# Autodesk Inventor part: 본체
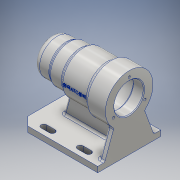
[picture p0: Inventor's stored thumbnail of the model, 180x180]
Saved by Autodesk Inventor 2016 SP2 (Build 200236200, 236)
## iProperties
Created: 2017-09
Part Number: 본체
Material: 알루미늄 6061
Document SubType Name: 모델링
Designer: Administrator
Density: 2.7 g/cm^3
Appearance: 알루미늄 - 평지
Sheet Metal Rule: 기본값_mm
Mass: 696.428 g
Surface Area: 709.296 cm^2
Volume: 257.936 cm^3
Author: Administrator
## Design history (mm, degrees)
sketch "스케치1"
  geometry: L1 (-56, -45)-(56, -45); L2 (56, -45)-(56, 45); L3 (56, 45)-(-56, 45); L4 (-56, 45)-(-56, -45); L5 (-56, -45)-(56, 45); L6 (56, -45)-(-56, 45); 1 further point
  constraints: 12 end point, 2 midpoint, 2 parallel, 1 horizontal, 1 perpendicular
  dimensions: "d0" = 112 distance of L2.end L3.end; "d1" = 90 distance of L1.end L2.end
extrude "돌출1" new body sketch "스케치1" distance "d2" = 8; taper "d3" = 0 deg
sketch "스케치4"
  geometry: L1 (56, 70)-(31, 70); L2 (31, 70)-(31, 95); L3 (31, 95)-(56, 95); L4 (56, 95)-(56, 70); L5 (31, 70)-(11, 70); L6 (11, 70)-(11, 97); L7 (11, 97)-(31, 97); L8 (31, 97)-(31, 70); L9 (11, 70)-(-28, 70); L10 (-28, 70)-(-28, 100); L11 (-28, 100)-(11, 100); L12 (11, 100)-(11, 70); L13 (-28, 70)-(-56, 70); L14 (-56, 70)-(-56, 104); L15 (-56, 104)-(-28, 104); L16 (-28, 104)-(-28, 70); L17 (-56, 0)-(-56, 8) reference; L18 (-56, 0)-(56, 0) reference; 1 further point
  constraints: 32 end point, 8 parallel, 4 horizontal, 4 perpendicular, 1 collinear
  dimensions: "d20" = 112 distance between parallel lines of L14 L4; "d21" = 25 distance of L2.end L3.end; "d22" = 45 distance between parallel lines of L6 L4; "d23" = 84 distance between parallel lines of L10 L4; "d24" = 70 distance between parallel lines of L18 L13; "d25" = 50 diameter of L3 L1; "d26" = 54 diameter of L7 L5; "d27" = 60 diameter of L11 L9; "d28" = 68 diameter of L15 L13
revolve "회전1" sketch "스케치4" stored, may be unused: angle "d29" = 90 deg
fillet "모깎기1" dims "d39" = 9
fillet "모깎기2" dims "d40" = 3
sketch "스케치7" dims "d52" = 0
  geometry: L1 (-56, 8)-(56, 8) reference; L2 (-56, 8)-(34, 8); L3 (34, 8)-(17.387, 70); L4 (17.387, 70)-(-56, 70); L5 (14, 97)-(14, 43) reference; L6 (-56, 70)-(-56, 8); L7 (-56, 0)-(56, 0) reference; L8 (56, 0)-(56, 8) reference; 1 further point
  constraints: 8 end point, 2 perpendicular, 1 point on line
  dimensions: "d41" = 70 distance between parallel lines of L7 L4; "d42" = 22 distance from line of L8 L2.end; "d43" = 105 deg angle of L1 L3
extrude "돌출5" join sketch "스케치7" stored distance "d44" = 8; taper "d45" = 0 deg
sketch "스케치8"
  geometry: L1 (-8, 90)-(-8, 0) reference; L2 (-8, 10)-(-70, 32.566); L3 (-70, 32.566)-(-70, 57.434); L4 (-70, 57.434)-(-8, 80); L5 (-8, 80)-(-8, 10); L6 (0, 0)-(-8, 0) reference; L7 (0, 90)-(-8, 90) reference; L8 (0, 90)-(0, 0) reference; 1 further point
  constraints: 8 end point, 2 point on line, 1 parallel, 1 vertical
  dimensions: "d46" = 10 distance from line of L6 L2.start; "d47" = 10 distance from line of L7 L4.end; "d48" = 110 deg angle of L1 L4; "d49" = 110 deg angle of L1 L2; "d50" = 70 distance between parallel lines of L8 L3
extrude "돌출6" join sketch "스케치8" distance "d51" = 8; taper "d52" = 0 deg
sketch "스케치9"
  geometry: L1 (-32, 34)-(-20, 34); L2 (-32, 30)-(-20, 30); L3 (-20, 38)-(-32, 38); L4 (20, 34)-(32, 34); L5 (20, 30)-(32, 30); L6 (32, 38)-(20, 38); L7 (56, -45)-(56, 45) reference; A1 r 4 centre (-32, 34) between (-32, 38) and (-32, 30); A2 r 4 centre (-20, 34) between (-20, 30) and (-20, 38); A3 r 4 centre (20, 34) between (20, 38) and (20, 30); A4 r 4 centre (32, 34) between (32, 30) and (32, 38); 3 further points
  constraints: 16 end point, 8 point on circle, 8 tangent, 4 centre point, 2 horizontal, 2 midpoint, 2 parallel, 1 horizontal alignment
  dimensions: "d53" = 34 vertical distance of point (0, 0) point (-26, 34); "d54" = 4 radius of A1; "d56" = 12 distance of L1.end L1.start; "d57" = 40 distance of L4.start L1.end; "d58" = 12 distance of L4.start L4.end; "d59" = 24 distance from line of L7 L4.end; "d60" = 4 radius of A3; "d61" = 4 radius of A2 (derived); "d62" = 4 radius of A4 (derived)
extrude "돌출7" cut sketch "스케치9" stored distance "d63" = 8; taper "d64" = 0 deg
chamfer "모따기1" distance "d65" = 12; stored, may be unused: second distance "d66" = 2, angle "d67" = 45 deg
sketch "스케치10"
  geometry: L1 (-56, 43.992)-(-56, 104) reference; L2 (-56, 70)-(-41, 70); L3 (-41, 70)-(-41, 91); L4 (-41, 91)-(-56, 91); L5 (-56, 91)-(-56, 70); L6 (-41, 70)-(13, 70); L7 (13, 70)-(13, 94); L8 (13, 94)-(-41, 94); L9 (-41, 94)-(-41, 70); L10 (13, 86.642)-(13, 70); L11 (-56, 0)-(44, 0) reference; L12 (13, 70)-(25, 70); L13 (25, 70)-(25, 91); L14 (25, 91)-(13, 91); L15 (13, 91)-(13, 70); L16 (25, 70)-(43, 70); L17 (43, 70)-(43, 87.5); L18 (43, 87.5)-(25, 87.5); L19 (25, 87.5)-(25, 70); L20 (43, 70)-(47, 70); L21 (47, 86)-(43, 86); L22 (43, 86)-(43, 70); L23 (47, 70)-(50, 70); L24 (50, 70)-(50, 80.5); L25 (50, 80.5)-(47, 80.5); L26 (47, 80.5)-(47, 70); L27 (47, 86)-(47, 70); L28 (47, 45)-(47, 95) reference; 1 further point
  constraints: 50 end point, 11 parallel, 6 horizontal, 5 perpendicular, 1 collinear, 1 point on line
  dimensions: "d68" = 70 distance between parallel lines of L11 L2; "d69" = 15 distance of L3.end L4.end; "d70" = 54 distance of L7.end L8.end; "d73" = 12 distance of L13.end L14.end; "d74" = 18 distance of L17.end L18.end; "d75" = 4 distance of L21.start L21.end; "d77" = 42 diameter of L4 L2; "d78" = 48 diameter of L8 L6; "d79" = 42 diameter of L14 L12; "d80" = 35 diameter of L18 L16; "d81" = 32 diameter of L21 L20; "d84" = 21 diameter of L25 L23; "d86" = 3 distance between parallel lines of L24 L27; "d105" = 7 distance between parallel lines of L22 L24 (derived)
revolve "회전2" sketch "스케치10" stored, may be unused: angle "d87" = 90 deg
fillet "모깎기3" dims "d88" = 3
fillet "모깎기4" dims "d89" = 0.3
fillet "모깎기5" dims "d90" = 3
chamfer "모따기2" distance "d91" = 1; stored, may be unused: second distance "d92" = 2, angle "d93" = 45 deg
sketch "스케치11" dims "d94" = 52
  geometry: C1 r 24 at (-70, 45) reference; C2 r 27 at (-70, 45) reference; 3 further points
  constraints: 1 coincident, 1 horizontal alignment, 2 other
hole "구멍1" sketch "스케치11" at (-96, 45) diameter "d95" = 3.242; stored, may be unused: countersink angle "d99" = 90 deg, drill point angle "d101" = 118 deg; dims "d96" = 8, "d97" = 4, "d98" = 2, "d100" = 11
fillet "모깎기6" dims "d106" = 3
sketch "스케치12"
  geometry: L1 (-176.004, 80.273)-(80.004, 80.273); L2 (80.004, 80.273)-(80.004, 59.727); L3 (80.004, 59.727)-(-176.004, 59.727); L4 (-176.004, 59.727)-(-176.004, 80.273); L5 (-176.004, 70)-(80.004, 70); L6 (-48, 70)-(-48, 59.727); L7 (-100, 0)-(0, 0) reference; L8 (0, 104)-(0, 45.289) reference; 1 further point
  constraints: 4 end point, 4 midpoint, 2 other
  dimensions: "d107" = 70 distance between parallel lines of L7 L5; "d108" = 48 distance between parallel lines of L8 L6
feature "엠보싱1" sketch "스케치12" dims "d20" = 112, "d21" = 25, "d22" = 45, "d23" = 84, "d24" = 70, "d25" = 50, "d26" = 54, "d27" = 60, "d28" = 68, "d109" = 0.5, "d110" = 0
node "솔리드1"
mirror "대칭1"
pattern_circular "원형 패턴1" dims angle "d103" = 360 deg
other parameters: "Thickness" = 0.5, "BendRadius" = 0.5 (= Thickness), "BendReliefWidth" = 0.5 (= Thickness), "BendReliefDepth" = 0.25 (= 0.5 x Thickness), "CornerReliefSize" = 2 (= 4 x Thickness), "SeamGap" = 0.01, "MinimumRemnant" = 1 (= 2 x Thickness), "TransitionRadius" = 0.5 (= BendRadius), "JacobiRadiusSize" = 0.5 (= BendRadius), "GapSize" = 0.5 (= Thickness)
